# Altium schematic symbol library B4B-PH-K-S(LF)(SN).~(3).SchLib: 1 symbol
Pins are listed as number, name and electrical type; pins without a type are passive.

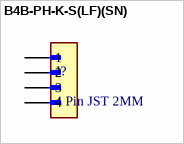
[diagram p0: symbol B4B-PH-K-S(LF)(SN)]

## B4B-PH-K-S(LF)(SN)
designator J?, comment 4 Pin JST 2MM
Connector Header Through Hole 4 position 0.079 (2.00mm); MF: JST Sales; MP: B4B-PH-K-S (LF)(SN)
footprint JST_B4B-PH-K-S(LF)(SN)
pins: 1, 2, 3, 4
